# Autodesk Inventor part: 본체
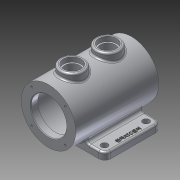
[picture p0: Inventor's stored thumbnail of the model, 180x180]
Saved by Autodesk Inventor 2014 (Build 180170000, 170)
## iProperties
Created: 2014-12
Part Number: 본체
Material: 알루미늄 6061
Document SubType Name: Modeling
Designer: Owner
Density: 2.71 g/cm^3
Appearance: 알루미늄 - 평지
Mass: 1293.91 g
Surface Area: 1040.15 cm^2
Volume: 477.456 cm^3
Author: Owner
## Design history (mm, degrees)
sketch "스케치1"
  geometry: C1 r 46 at (0, 0); 1 further point
  constraints: 1 centre point, 1 coincident
  dimensions: "d0" = 92 diameter of C1
extrude "돌출1" new body sketch "스케치1" stored distance "d1" = 140; taper "d2" = 0 deg
sketch "스케치2"
  geometry: C1 r 46 at (0, 0) reference; C2 r 30 at (0, 0)
  constraints: 1 centre point, 1 coincident
  dimensions: "d3" = 60 diameter of C2
extrude "돌출2" cut sketch "스케치2" distance "d4" = 12; taper "d5" = 0 deg
sketch "스케치3"
  geometry: C1 r 46 at (0, 0) reference; C2 r 30 at (0, 0)
  constraints: 1 centre point, 1 coincident
  dimensions: "d6" = 60 diameter of C2
extrude "돌출3" cut sketch "스케치3" distance "d7" = 12; taper "d8" = 0 deg
sketch "스케치4"
  geometry: C1 r 30 at (0, 0) reference; C2 r 37.5 at (0, 0)
  constraints: 1 centre point, 1 coincident
  dimensions: "d9" = 75 diameter of C2
extrude "돌출4" cut sketch "스케치4" distance "d10" = 116; taper "d11" = 0 deg
node "작업 평면2"
sketch "스케치7"
  geometry: L1 (-46, -70)-(46, -70) reference; C1 r 20 at (0, -30); C2 r 20 at (0, 30); 1 further point
  constraints: 2 centre point, 2 vertical alignment
  dimensions: "d20" = 40 distance from line of C1.centre L1; "d21" = 60 distance of C2.centre C1.centre; "d22" = 40 diameter of C2; "d23" = 40 diameter of C1
extrude "돌출6" join sketch "스케치7" stored distance "d24" = 80; taper "d25" = 0 deg
sketch "스케치8"
  geometry: C1 r 20 at (0, 0) reference; C2 r 15 at (0, 0); 1 further point
  constraints: 1 centre point, 1 coincident
  dimensions: "d26" = 30 diameter of C2
extrude "돌출7" cut sketch "스케치8" distance "d27" = 8; taper "d28" = 0 deg
sketch "스케치9"
  geometry: C1 r 15 at (0, 0) reference; C2 r 12.5 at (0, 0); 1 further point
  constraints: 1 centre point, 1 coincident
  dimensions: "d29" = 25 diameter of C2
extrude "돌출8" cut sketch "스케치9" stored distance "d30" = 8; taper "d31" = 0 deg
node "작업 평면3"
sketch "스케치10"
  geometry: L1 (-65, 55)-(65, 55); L2 (65, 55)-(65, -40); L3 (65, -40)-(-65, -40); L4 (-65, -40)-(-65, 55); L5 (46, 70)-(-46, 70) reference; 3 further points
  constraints: 8 end point, 2 midpoint, 2 parallel, 1 horizontal, 1 perpendicular, 1 vertical alignment
  dimensions: "d33" = 15 distance between parallel lines of L5 L1; "d34" = 95 distance of L3.end L1.start; "d35" = 130 distance of L1.start L1.end
extrude "돌출9" join sketch "스케치10" distance "d36" = 12; taper "d37" = 0 deg
sketch "스케치11"
  geometry: L1 (65, -40)-(65, 55) reference; L2 (65, 55)-(25.923, 55) reference; C1 r 5.5 at (52, 42.5); 1 further point
  constraints: 1 centre point
  dimensions: "d38" = 12.5 distance from line of C1.centre L2; "d39" = 13 distance from line of L1 C1.centre; "d45" = 11 diameter of C1
extrude "돌출10" cut sketch "스케치11" stored distance "d40" = 12; taper "d41" = 0 deg
fillet "모깎기1" dims "d46" = 10
chamfer "모따기1" distance "d47" = 1; stored, may be unused: second distance "d48" = 2, angle "d49" = 45 deg
fillet "모깎기2" dims "d61" = 3
fillet "모깎기5" dims "d64" = 3
fillet "모깎기6" dims "d65" = 3
sketch "스케치13"
  geometry: L1 (65, -30)-(65, 45) reference; C1 r 5.5 at (52, -27.5) reference; 2 further points
  constraints: 1 other
  dimensions: "d66" = 8 distance from line of L1 point (57, 7.5); "d67" = 35 vertical distance of C1.centre point (57, 7.5)
feature "엠보싱1" sketch "스케치13" dims "d68" = 1, "d69" = 0
sketch "스케치14"
  geometry: L1 (0, 0)-(28.284, 28.284); L2 (0, 0)-(40, 0); C1 r 31 at (0, 0) reference; 1 further point
  constraints: 4 end point, 1 coincident, 1 equal length, 1 horizontal
  dimensions: "d74" = 40 distance of L1.start L1.end; "d75" = 45 deg angle of L2 L1
hole "구멍2" sketch "스케치14" at (28.284, 28.284) diameter "d76" = 3.242; stored, may be unused: countersink angle "d80" = 90 deg, drill point angle "d82" = 118 deg; dims "d77" = 9, "d78" = 4, "d79" = 2, "d81" = 10
fillet "모깎기8" dims "d86" = 5
fillet "모깎기9" dims "d87" = 3
fillet "모깎기10" dims "d88" = 3
node "솔리드1"
mirror "대칭1"
mirror "대칭4"
pattern_circular "원형 패턴2" dims angle "d84" = 360 deg
mirror "대칭5"
pattern_linear "직사각형 패턴3" dims "d91" = 70
pattern_linear "직사각형 패턴4" dims "d94" = 104
other parameters: "d19" = 56
